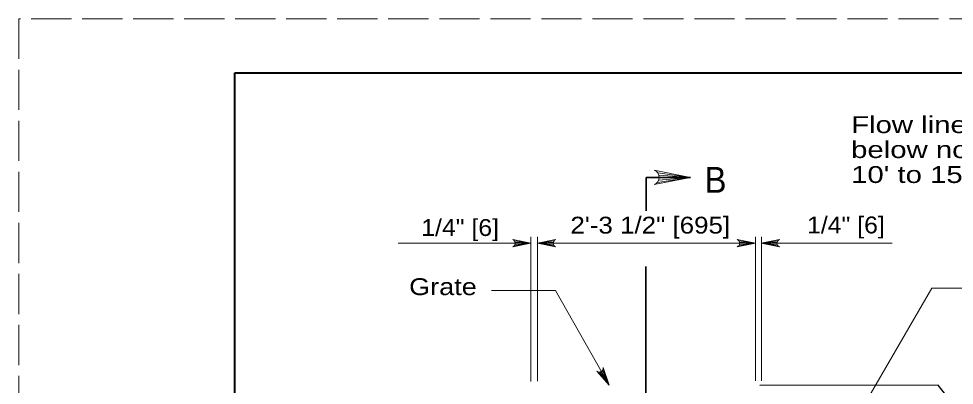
# Model space of a CAD drawing. Extents: x 1329.9 to 1363.9, y 715.5 to 737.5.
# Drawn here: x 1329.86 to 1338.52, y 734.11 to 737.5 of the extents above; entities that cross this region are included whole.
import ezdxf
from ezdxf.enums import TextEntityAlignment as Align

# ---------------------------------------------------------------- set-up
doc = ezdxf.new("R2010")
doc.units = 0
doc.header["$LTSCALE"] = 0.062
doc.linetypes.add('LONG_DASHED', pattern=[7.5, 6, -1.5])
doc.layers.add('1', color=7, linetype='Continuous', lineweight=13)

msp = doc.modelspace()

# ---------------------------------------------------------------- linework, layer by layer
at = {"layer": '1', "lineweight": 25}
msp.add_line((1331.86333, 736.9975), (1363.36333, 736.9975), dxfattribs=at)
at = {"layer": '1', "lineweight": 35}
for p, q in [((1335.66942, 736.03), (1336.08058, 736.03)), ((1335.66942, 736.03), (1335.66942, 735.7195)), ((1335.66467, 735.20608), (1335.66467, 733.44408))]:
    msp.add_line(p, q, dxfattribs=at)
at = {"layer": '1'}
for p, q in [((1335.77242, 735.98292), (1336.08058, 736.03)), ((1335.776, 736.07258), (1336.08058, 736.03)), ((1335.78408, 736.00258), (1336.08058, 736.03)), ((1335.78633, 736.0515), (1336.08058, 736.03)), ((1335.7895, 736.03), (1336.08058, 736.03)), ((1334.6025, 734.14283), (1334.6025, 735.47933)), ((1334.663, 734.14592), (1334.663, 735.47933)), ((1336.6815, 734.14667), (1336.6815, 735.47933)), ((1336.73492, 734.14625), (1336.73492, 735.47933)), ((1333.37567, 735.42075), (1334.6025, 735.42075)), ((1334.44875, 735.39725), (1334.60283, 735.42075)), ((1334.4505, 735.44208), (1334.60283, 735.42075)), ((1334.45458, 735.40708), (1334.60283, 735.42075)), ((1334.45567, 735.43158), (1334.60283, 735.42075)), ((1334.45725, 735.42075), (1334.60283, 735.42075)), ((1334.49717, 735.42075), (1334.59617, 735.42075)), ((1334.663, 735.42075), (1335.93717, 735.42075)), ((1334.8155, 735.44208), (1334.66317, 735.42075)), ((1334.81033, 735.43158), (1334.66317, 735.42075)), ((1334.80875, 735.42075), (1334.66317, 735.42075)), ((1334.81142, 735.40708), (1334.66317, 735.42075)), ((1334.81725, 735.39725), (1334.66317, 735.42075)), ((1334.76442, 735.42075), (1334.66542, 735.42075)), ((1335.93717, 735.42075), (1336.6815, 735.42075)), ((1336.52608, 735.39725), (1336.68017, 735.42075)), ((1336.52783, 735.44208), (1336.68017, 735.42075)), ((1336.53192, 735.40708), (1336.68017, 735.42075)), ((1336.533, 735.43158), (1336.68017, 735.42075)), ((1336.53458, 735.42075), (1336.68017, 735.42075)), ((1336.57358, 735.42075), (1336.67258, 735.42075)), ((1336.88633, 735.44208), (1336.73408, 735.42075)), ((1336.88117, 735.43158), (1336.73408, 735.42075)), ((1336.87958, 735.42075), (1336.73408, 735.42075)), ((1336.88233, 735.40708), (1336.73408, 735.42075)), ((1336.88817, 735.39725), (1336.73408, 735.42075)), ((1336.73492, 735.42075), (1337.94575, 735.42075)), ((1335.23267, 734.22942), (1335.326, 734.10725)), ((1335.24433, 734.23008), (1335.326, 734.10725)), ((1335.2545, 734.23408), (1335.326, 734.10725)), ((1335.26508, 734.24308), (1335.326, 734.10725)), ((1335.27083, 734.253), (1335.326, 734.10725))]:
    msp.add_line(p, q, dxfattribs=at)
at = {"layer": '1', "linetype": 'LONG_DASHED'}
msp.add_lwpolyline([(1329.86333, 715.4975), (1363.86333, 715.4975), (1363.86333, 737.4975), (1329.86333, 737.4975)], close=True, dxfattribs=at)
at = {"layer": '1', "lineweight": 25}
for points in [[(1363.36333, 715.9975), (1331.86333, 715.9975), (1331.86333, 736.9975)], [(1338.4845, 733.53708), (1338.4845, 733.96325), (1338.37, 734.1075), (1336.72025, 734.10508)]]:
    msp.add_lwpolyline(points, dxfattribs=at)
at = {"layer": '1', "lineweight": 40}
msp.add_lwpolyline([(1331.86333, 736.9975), (1363.36333, 736.9975), (1363.36333, 715.9975), (1331.86333, 715.9975)], close=True, dxfattribs=at)
msp.add_lwpolyline([(1331.86333, 736.9975), (1363.36333, 736.9975), (1363.36333, 715.9975), (1331.86333, 715.9975)], close=True, dxfattribs=at)
at = {"layer": '1'}
for points in [[(1335.74417, 735.96267), (1336.08058, 736.03), (1335.74417, 736.09725)], [(1334.43458, 735.38717), (1334.60283, 735.42075), (1334.43458, 735.45442)], [(1334.83142, 735.38717), (1334.66317, 735.42075), (1334.83142, 735.45442)], [(1336.51192, 735.38717), (1336.68017, 735.42075), (1336.51192, 735.45442)], [(1336.90225, 735.38717), (1336.73408, 735.42075), (1336.90225, 735.45442)], [(1335.326, 734.10725), (1334.8315, 734.98242), (1334.23875, 734.98242)], [(1338.59067, 735.00633), (1338.312, 735.00633), (1337.42808, 733.47783)], [(1335.27267, 734.27033), (1335.326, 734.10725), (1335.21408, 734.23725)]]:
    msp.add_lwpolyline(points, dxfattribs=at)
for centre, radius, start, end in [((1335.717, 736.03005), 0.07261, 292.08605, 67.91218), ((1334.421, 735.42083), 0.03631, 292.08605, 67.91218), ((1334.84499, 735.42083), 0.03631, 112.08782, 247.91395), ((1336.49836, 735.42083), 0.03631, 292.08605, 67.91218), ((1336.91585, 735.42083), 0.03631, 112.08782, 247.91395), ((1335.23665, 734.26558), 0.03631, 231.51682, 7.34295)]:
    msp.add_arc(centre, radius, start, end, dxfattribs=at)

# ---------------------------------------------------------------- texts
for s, width, p in [('Flow line to be 4" to 6" [100 to 150]', 1.3, (1337.56558, 736.43942)), ('below normal ditch, returning to normal', 1.3, (1337.56558, 736.20867)), ("10' to 15' [3 to 5 m] each side of basin.", 1.3, (1337.56558, 735.97792)), ('Grate', 1.2, (1333.47583, 734.94075))]:
    msp.add_text(s, height=0.156, dxfattribs=dict(at, width=width)).set_placement(p)
for s, height, width, p in [('B', 0.24, 0.95, (1336.31067, 735.88683)), ('1/4" [6]', 0.156, 1.1, (1333.94763, 735.48783)), ('2\'-3 1/2" [695]', 0.156, 1.15, (1335.70708, 735.50975)), ('1/4" [6]', 0.156, 1.1, (1337.51754, 735.51158))]:
    msp.add_text(s, height=height, dxfattribs=dict(at, width=width)).set_placement(p, align=Align.CENTER)

doc.saveas('drawing.dxf')
